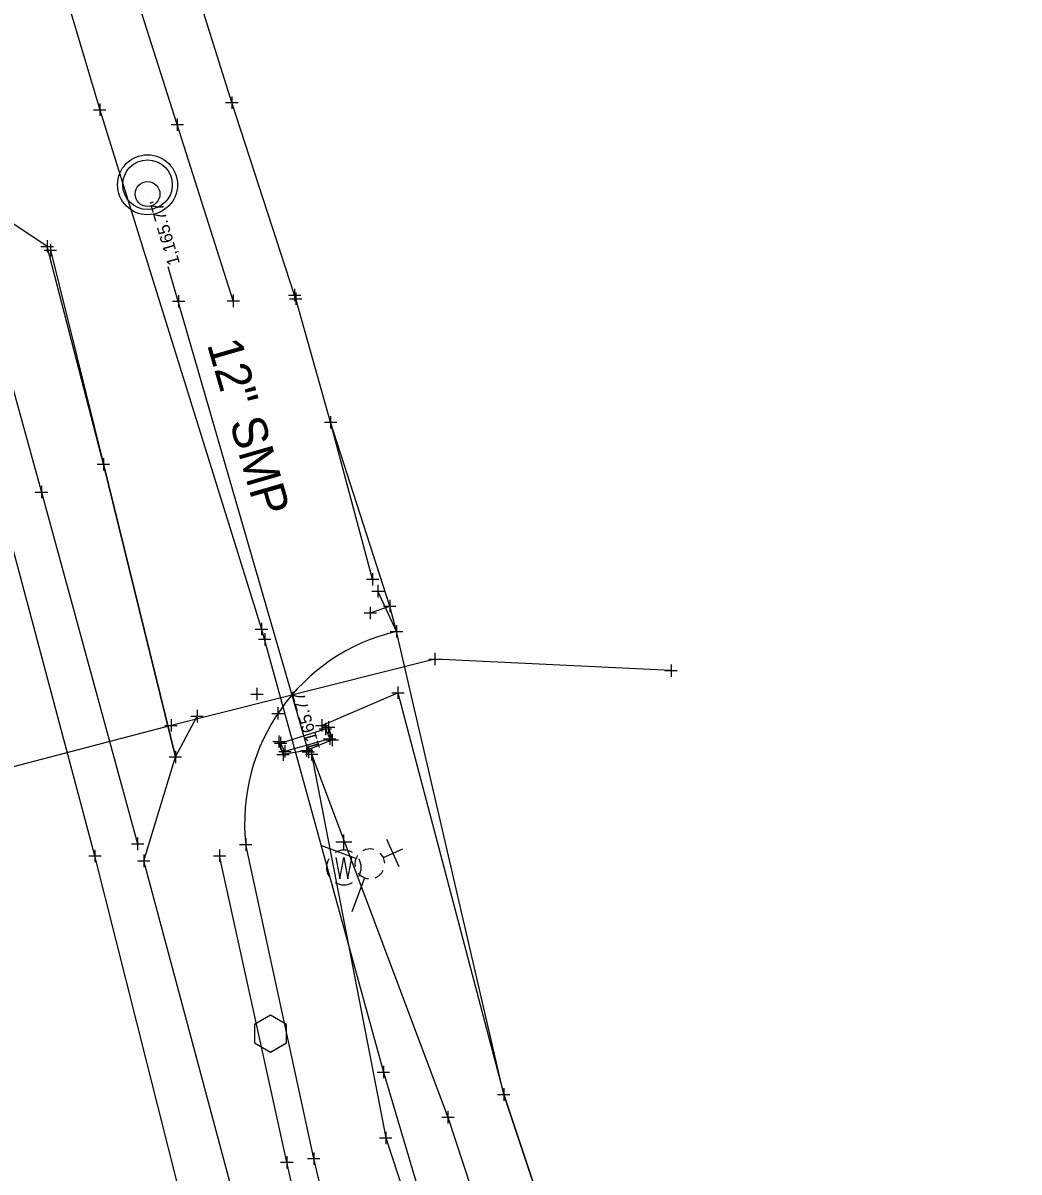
# Model space of a CAD drawing. Extents: x 2324380 to 2325559, y 691096 to 693386.
# Drawn here: x 2325128.4 to 2325208.8, y 691972.1 to 692064.7 of the extents above; entities that cross this region are included whole.
import ezdxf

# ---------------------------------------------------------------- set-up
doc = ezdxf.new("R2010")
doc.units = 0
for name, color, linetype in [('DR_X_Cells', 7, 'Continuous'), ('DR_X_Elev_Flow', 7, 'Continuous'), ('DR_X_Headwall', 7, 'Continuous'), ('DR_X_Storm_Sewer', 7, 'Continuous'), ('DR_X_Text', 7, 'Continuous'), ('GK_Drainage_Nodes', 7, 'Continuous'), ('PM_X_Transverse_Line', 7, 'Continuous'), ('PV_X_Driveway', 7, 'Continuous'), ('PV_X_EOP', 7, 'Continuous'), ('PV_X_Shoulder_Aggregate', 7, 'Continuous'), ('PV_X_Walk', 7, 'Continuous'), ('RD_X_Cells', 7, 'Continuous'), ('RD_X_GR_Rt', 7, 'Continuous'), ('SC_Scratch1', 7, 'Continuous'), ('SV_X_Break_Lines', 7, 'Continuous'), ('SV_X_Shot_Marker', 7, 'Continuous'), ('SV_X_Terrain_Boundary', 7, 'Continuous'), ('SV_X_Toe_of_Slope', 7, 'Continuous'), ('SV_X_Top_of_Bank', 7, 'Continuous'), ('UT_X_Gas', 7, 'Continuous'), ('UT_X_Water', 7, 'Continuous'), ('UT_X_Water_Cells', 7, 'Continuous')]:
    doc.layers.add(name, color=color, linetype=linetype)

msp = doc.modelspace()

# ---------------------------------------------------------------- linework, layer by layer
at = {"layer": 'DR_X_Cells'}
for centre, radius in [((2325138.489, 692051.697), 2.417), ((2325138.489, 692051.697), 2), ((2325138.489, 692050.947), 1)]:
    msp.add_circle(centre, radius, dxfattribs=at)
at = {"layer": 'DR_X_Elev_Flow'}
for p, q in [((2325151.459, 692006.478), (2325151.459, 692005.478)), ((2325150.959, 692005.978), (2325151.959, 692005.978)), ((2325151.459, 692005.978), (2325151.459, 692005.978))]:
    msp.add_line(p, q, dxfattribs=at)
at = {"layer": 'DR_X_Headwall'}
msp.add_lwpolyline([(2325152.828, 692007.837), (2325153.185, 692007.047), (2325149.569, 692006.028), (2325149.216, 692006.692)], close=True, dxfattribs=at)
at = {"layer": 'DR_X_Storm_Sewer'}
msp.add_line((2325151.459, 692005.978), (2325140.151, 692045.092), dxfattribs=at)
at = {"layer": 'GK_Drainage_Nodes'}
for p, q in [((2325138.489, 692053.697), (2325138.489, 692053.697)), ((2325138.489, 692051.697), (2325138.489, 692051.697)), ((2325138.489, 692051.697), (2325138.489, 692051.697)), ((2325138.489, 692050.947), (2325138.489, 692050.947)), ((2325138.489, 692049.697), (2325138.489, 692049.697))]:
    msp.add_line(p, q, dxfattribs=at)
msp.add_circle((2325138.489, 692051.697), 2, dxfattribs=at)
at = {"layer": 'PM_X_Transverse_Line'}
msp.add_lwpolyline([(2325208.031, 691604.619), (2325194.767, 691694.589), (2325190.218, 691721.345), (2325186.042, 691748.471), (2325180.662, 691777.723), (2325175.443, 691810.812), (2325170.122, 691836.608), (2325164.914, 691862.726), (2325159.595, 691887.988), (2325154.325, 691913.687), (2325148, 691940.383), (2325141.011, 691970.752), (2325134.246, 691997.599), (2325126.612, 692026.24), (2325119.986, 692049.571), (2325112.237, 692077.635)], dxfattribs=at)
at = {"layer": 'PV_X_Driveway'}
for p, q in [((2325130.663, 692046.423), (2325134.934, 692029.169)), ((2325153.247, 692032.554), (2325150.44, 692042.514)), ((2325156.635, 692019.901), (2325153.247, 692032.554)), ((2325134.934, 692029.169), (2325140.741, 692005.582)), ((2325140.741, 692005.582), (2325142.488, 692008.863))]:
    msp.add_line(p, q, dxfattribs=at)
at = {"layer": 'PV_X_EOP'}
msp.add_lwpolyline([(2325211.918, 691605.386), (2325210.367, 691618.546), (2325213.959, 691624.804), (2325210.034, 691657.833), (2325203.565, 691662.571), (2325202.33, 691668.932), (2325198.243, 691695.477), (2325193.907, 691721.989), (2325189.381, 691749.914), (2325184.426, 691778.627), (2325178.884, 691811.262), (2325173.941, 691837.313), (2325168.715, 691863.962), (2325163.821, 691888.364), (2325158.392, 691913.65), (2325152.294, 691941.349), (2325145.116, 691971.334), (2325138.187, 691997.205), (2325140.741, 692005.582), (2325134.934, 692029.169), (2325130.398, 692046.728), (2325123.251, 692051.464), (2325115.822, 692078.513)], dxfattribs=at)
at = {"layer": 'PV_X_Shoulder_Aggregate'}
for p, q in [((2325158.563, 692015.701), (2325157.064, 692018.938)), ((2325151.891, 691973.202), (2325146.411, 691998.522)), ((2325159.251, 691943.083), (2325151.891, 691973.202))]:
    msp.add_line(p, q, dxfattribs=at)
msp.add_arc((2325162.181, 692000.254), 15.865, 103.18124, 186.26782, dxfattribs=at)
at = {"layer": 'PV_X_Walk'}
for points in [[(2325150.345, 692042.806), (2325145.287, 692058.32), (2325137.022, 692084.694), (2325126.836, 692114.846), (2325122.507, 692126.861)], [(2325145.407, 692042.338), (2325140.889, 692056.549), (2325132.558, 692082.735), (2325122.132, 692113.395), (2325118.749, 692123.303)]]:
    msp.add_lwpolyline(points, dxfattribs=at)
at = {"layer": 'RD_X_Cells'}
msp.add_lwpolyline([(2325147.104, 691982.524), (2325148.402, 691981.774), (2325149.7, 691982.524), (2325149.7, 691984.024), (2325148.402, 691984.774), (2325147.104, 691984.024), (2325147.104, 691982.524)], dxfattribs=at)
at = {"layer": 'RD_X_GR_Rt'}
for p, q in [((2325156.447, 692017.186), (2325158.021, 692017.741)), ((2325149.72, 691972.915), (2325144.303, 691997.622)), ((2325156.653, 691942.344), (2325149.72, 691972.915))]:
    msp.add_line(p, q, dxfattribs=at)
at = {"layer": 'SV_X_Break_Lines'}
for points in [[(2325123.247, 692051.066), (2325129.941, 692026.924), (2325137.687, 691998.578)], [(2325153.081, 692007.969), (2325153.381, 692006.955), (2325151.312, 692006.096), (2325149.417, 692005.778), (2325149.087, 692006.813)]]:
    msp.add_lwpolyline(points, dxfattribs=at)
at = {"layer": 'SV_X_Shot_Marker'}
for p, q in [((2325145.287, 692058.82), (2325145.287, 692057.82)), ((2325134.639, 692058.245), (2325134.639, 692057.245)), ((2325144.787, 692058.32), (2325145.787, 692058.32)), ((2325145.287, 692058.32), (2325145.287, 692058.32)), ((2325134.139, 692057.745), (2325135.139, 692057.745)), ((2325134.639, 692057.745), (2325134.639, 692057.745)), ((2325140.889, 692057.049), (2325140.889, 692056.049)), ((2325140.389, 692056.549), (2325141.389, 692056.549)), ((2325140.889, 692056.549), (2325140.889, 692056.549)), ((2325130.398, 692047.228), (2325130.398, 692046.228)), ((2325130.663, 692046.923), (2325130.663, 692045.923)), ((2325129.898, 692046.728), (2325130.898, 692046.728)), ((2325130.163, 692046.423), (2325131.163, 692046.423)), ((2325130.398, 692046.728), (2325130.398, 692046.728)), ((2325130.663, 692046.423), (2325130.663, 692046.423)), ((2325150.345, 692043.306), (2325150.345, 692042.306)), ((2325140.497, 692042.302), (2325141.497, 692042.302)), ((2325140.997, 692042.802), (2325140.997, 692041.802)), ((2325140.997, 692042.302), (2325140.997, 692042.302)), ((2325144.907, 692042.338), (2325145.907, 692042.338)), ((2325145.407, 692042.838), (2325145.407, 692041.838)), ((2325145.407, 692042.338), (2325145.407, 692042.338)), ((2325149.845, 692042.806), (2325150.845, 692042.806)), ((2325149.94, 692042.514), (2325150.94, 692042.514)), ((2325150.345, 692042.806), (2325150.345, 692042.806)), ((2325150.44, 692043.014), (2325150.44, 692042.014)), ((2325150.44, 692042.514), (2325150.44, 692042.514)), ((2325153.247, 692033.054), (2325153.247, 692032.054)), ((2325152.747, 692032.554), (2325153.747, 692032.554)), ((2325153.247, 692032.554), (2325153.247, 692032.554)), ((2325134.934, 692029.669), (2325134.934, 692028.669)), ((2325134.934, 692029.669), (2325134.934, 692028.669)), ((2325134.434, 692029.169), (2325135.434, 692029.169)), ((2325134.434, 692029.169), (2325135.434, 692029.169)), ((2325134.934, 692029.169), (2325134.934, 692029.169)), ((2325134.934, 692029.169), (2325134.934, 692029.169)), ((2325129.941, 692027.424), (2325129.941, 692026.424)), ((2325129.441, 692026.924), (2325130.441, 692026.924)), ((2325129.941, 692026.924), (2325129.941, 692026.924)), ((2325156.635, 692020.401), (2325156.635, 692019.401)), ((2325156.135, 692019.901), (2325157.135, 692019.901)), ((2325156.635, 692019.901), (2325156.635, 692019.901)), ((2325157.064, 692019.438), (2325157.064, 692018.438)), ((2325156.564, 692018.938), (2325157.564, 692018.938)), ((2325157.064, 692018.938), (2325157.064, 692018.938)), ((2325158.021, 692018.241), (2325158.021, 692017.241)), ((2325155.947, 692017.186), (2325156.947, 692017.186)), ((2325156.447, 692017.686), (2325156.447, 692016.686)), ((2325156.447, 692017.186), (2325156.447, 692017.186)), ((2325157.521, 692017.741), (2325158.521, 692017.741)), ((2325158.021, 692017.741), (2325158.021, 692017.741)), ((2325147.677, 692016.387), (2325147.677, 692015.387)), ((2325147.177, 692015.887), (2325148.177, 692015.887)), ((2325147.677, 692015.887), (2325147.677, 692015.887)), ((2325147.935, 692015.561), (2325147.935, 692014.561)), ((2325158.063, 692015.701), (2325159.063, 692015.701)), ((2325158.563, 692016.201), (2325158.563, 692015.201)), ((2325158.563, 692015.701), (2325158.563, 692015.701)), ((2325147.435, 692015.061), (2325148.435, 692015.061)), ((2325147.935, 692015.061), (2325147.935, 692015.061)), ((2325161.167, 692013.468), (2325162.167, 692013.468)), ((2325161.667, 692013.968), (2325161.667, 692012.968)), ((2325161.667, 692013.468), (2325161.667, 692013.468)), ((2325180.199, 692012.533), (2325181.199, 692012.533)), ((2325180.699, 692013.033), (2325180.699, 692012.033)), ((2325180.699, 692012.533), (2325180.699, 692012.533)), ((2325147.308, 692011.149), (2325147.308, 692010.149)), ((2325158.174, 692010.756), (2325159.174, 692010.756)), ((2325158.674, 692011.256), (2325158.674, 692010.256)), ((2325158.674, 692010.756), (2325158.674, 692010.756)), ((2325146.808, 692010.649), (2325147.808, 692010.649)), ((2325147.308, 692010.649), (2325147.308, 692010.649)), ((2325141.988, 692008.863), (2325142.988, 692008.863)), ((2325142.488, 692009.363), (2325142.488, 692008.363)), ((2325142.488, 692008.863), (2325142.488, 692008.863)), ((2325148.504, 692009.09), (2325149.504, 692009.09)), ((2325149.004, 692009.59), (2325149.004, 692008.59)), ((2325149.004, 692009.09), (2325149.004, 692009.09)), ((2325139.885, 692008.126), (2325140.885, 692008.126)), ((2325140.385, 692008.626), (2325140.385, 692007.626)), ((2325140.385, 692008.126), (2325140.385, 692008.126)), ((2325152.044, 692008.126), (2325153.044, 692008.126)), ((2325152.544, 692008.626), (2325152.544, 692007.626)), ((2325152.544, 692008.126), (2325152.544, 692008.126)), ((2325152.581, 692007.969), (2325153.581, 692007.969)), ((2325152.828, 692008.337), (2325152.828, 692007.337)), ((2325153.081, 692008.469), (2325153.081, 692007.469)), ((2325153.081, 692007.969), (2325153.081, 692007.969)), ((2325149.087, 692007.313), (2325149.087, 692006.313)), ((2325149.216, 692007.192), (2325149.216, 692006.192)), ((2325152.328, 692007.837), (2325153.328, 692007.837)), ((2325152.685, 692007.047), (2325153.685, 692007.047)), ((2325152.828, 692007.837), (2325152.828, 692007.837)), ((2325153.185, 692007.547), (2325153.185, 692006.547)), ((2325153.185, 692007.047), (2325153.185, 692007.047)), ((2325153.381, 692007.455), (2325153.381, 692006.455)), ((2325140.741, 692006.082), (2325140.741, 692005.082)), ((2325140.741, 692006.082), (2325140.741, 692005.082)), ((2325148.587, 692006.813), (2325149.587, 692006.813)), ((2325148.716, 692006.692), (2325149.716, 692006.692)), ((2325149.087, 692006.813), (2325149.087, 692006.813)), ((2325149.216, 692006.692), (2325149.216, 692006.692)), ((2325149.417, 692006.278), (2325149.417, 692005.278)), ((2325149.569, 692006.528), (2325149.569, 692005.528)), ((2325150.812, 692006.096), (2325151.812, 692006.096)), ((2325151.312, 692006.596), (2325151.312, 692005.596)), ((2325151.312, 692006.096), (2325151.312, 692006.096)), ((2325151.717, 692006.298), (2325151.717, 692005.298)), ((2325151.717, 692006.298), (2325151.717, 692005.298)), ((2325152.881, 692006.955), (2325153.881, 692006.955)), ((2325153.381, 692006.955), (2325153.381, 692006.955)), ((2325140.241, 692005.582), (2325141.241, 692005.582)), ((2325140.241, 692005.582), (2325141.241, 692005.582)), ((2325140.741, 692005.582), (2325140.741, 692005.582)), ((2325140.741, 692005.582), (2325140.741, 692005.582)), ((2325148.917, 692005.778), (2325149.917, 692005.778)), ((2325149.069, 692006.028), (2325150.069, 692006.028)), ((2325149.417, 692005.778), (2325149.417, 692005.778)), ((2325149.569, 692006.028), (2325149.569, 692006.028)), ((2325151.217, 692005.798), (2325152.217, 692005.798)), ((2325151.217, 692005.798), (2325152.217, 692005.798)), ((2325151.717, 692005.798), (2325151.717, 692005.798)), ((2325151.717, 692005.798), (2325151.717, 692005.798)), ((2325137.687, 691999.078), (2325137.687, 691998.078)), ((2325146.411, 691999.022), (2325146.411, 691998.022)), ((2325134.246, 691998.099), (2325134.246, 691997.099)), ((2325137.187, 691998.578), (2325138.187, 691998.578)), ((2325137.687, 691998.578), (2325137.687, 691998.578)), ((2325138.187, 691997.705), (2325138.187, 691996.705)), ((2325144.303, 691998.122), (2325144.303, 691997.122)), ((2325145.911, 691998.522), (2325146.911, 691998.522)), ((2325146.411, 691998.522), (2325146.411, 691998.522)), ((2325133.746, 691997.599), (2325134.746, 691997.599)), ((2325134.246, 691997.599), (2325134.246, 691997.599)), ((2325137.687, 691997.205), (2325138.687, 691997.205)), ((2325138.187, 691997.205), (2325138.187, 691997.205)), ((2325143.803, 691997.622), (2325144.803, 691997.622)), ((2325144.303, 691997.622), (2325144.303, 691997.622)), ((2325157.011, 691980.18), (2325158.011, 691980.18)), ((2325157.511, 691980.68), (2325157.511, 691979.68)), ((2325157.511, 691980.18), (2325157.511, 691980.18)), ((2325166.706, 691978.375), (2325167.706, 691978.375)), ((2325167.206, 691978.875), (2325167.206, 691977.875)), ((2325167.206, 691978.375), (2325167.206, 691978.375)), ((2325162.21, 691976.546), (2325163.21, 691976.546)), ((2325162.71, 691977.046), (2325162.71, 691976.046)), ((2325162.71, 691976.546), (2325162.71, 691976.546)), ((2325157.191, 691974.871), (2325158.191, 691974.871)), ((2325157.691, 691975.371), (2325157.691, 691974.371)), ((2325157.691, 691974.871), (2325157.691, 691974.871)), ((2325151.891, 691973.702), (2325151.891, 691972.702)), ((2325149.22, 691972.915), (2325150.22, 691972.915)), ((2325149.72, 691973.415), (2325149.72, 691972.415)), ((2325149.72, 691972.915), (2325149.72, 691972.915)), ((2325151.391, 691973.202), (2325152.391, 691973.202)), ((2325151.891, 691973.202), (2325151.891, 691973.202))]:
    msp.add_line(p, q, dxfattribs=at)
at = {"layer": 'SV_X_Terrain_Boundary'}
msp.add_lwpolyline([(2325352.933, 691883.659), (2325255.311, 691863.891), (2325186.043, 691921.872), (2325167.206, 691978.375), (2325158.563, 692015.701), (2325158.021, 692017.741), (2325153.247, 692032.554), (2325150.44, 692042.514), (2325150.345, 692042.806), (2325145.287, 692058.32), (2325137.022, 692084.694)], dxfattribs=at)
at = {"layer": 'SV_X_Toe_of_Slope'}
for points in [[(2325151.717, 692005.798), (2325157.691, 691974.871), (2325176.194, 691918.403), (2325187.809, 691869.152), (2325196.671, 691845.991), (2325199.142, 691833.728)], [(2325151.717, 692005.798), (2325162.71, 691976.546), (2325181.201, 691920.276), (2325195.806, 691870.258), (2325202.361, 691849.073), (2325202.361, 691835.591)]]:
    msp.add_lwpolyline(points, dxfattribs=at)
at = {"layer": 'SV_X_Top_of_Bank'}
msp.add_lwpolyline([(2325152.544, 692008.126), (2325158.674, 692010.756), (2325167.206, 691978.375), (2325186.043, 691921.872), (2325201.379, 691871.384), (2325207.218, 691852.964), (2325225.302, 691856.36), (2325255.311, 691863.891)], dxfattribs=at)
at = {"layer": 'UT_X_Gas'}
msp.add_lwpolyline([(2325180.699, 692012.533), (2325161.667, 692013.468), (2325140.385, 692008.126), (2325120.132, 692002.823), (2325102.157, 691998.254), (2325087.784, 691995.252)], dxfattribs=at)
at = {"layer": 'UT_X_Water'}
msp.add_lwpolyline([(2325124.52, 692091.666), (2325134.639, 692057.745), (2325147.677, 692015.887), (2325157.511, 691980.18), (2325171.318, 691933.622), (2325182.702, 691894.576), (2325195.308, 691848.427), (2325206.623, 691806.006), (2325210.43, 691786.813), (2325214.153, 691760.189), (2325217.411, 691715.895), (2325220.598, 691667.669), (2325222.982, 691628.174), (2325224.503, 691603.216), (2325224.967, 691587.75)], dxfattribs=at)
at = {"layer": 'UT_X_Water_Cells'}
for p, q in [((2325154.956, 691998.702), (2325153.684, 691998.702)), ((2325154.321, 691998.065), (2325154.321, 691999.337)), ((2325158.786, 691996.727), (2325157.793, 691998.912)), ((2325155.289, 691997.384), (2325152.537, 691998.417)), ((2325157.507, 691997.463), (2325159.073, 691998.175)), ((2325156.412, 691996.964), (2325156.412, 691996.964)), ((2325156.412, 691996.964), (2325156.412, 691996.964)), ((2325154.321, 691996.665), (2325154.321, 691996.665)), ((2325155.989, 691995.844), (2325154.958, 691993.09))]:
    msp.add_line(p, q, dxfattribs=at)
msp.add_lwpolyline([(2325153.684, 691997.485), (2325154.003, 691995.762), (2325154.321, 691997.485), (2325154.641, 691995.762), (2325154.958, 691997.485)], dxfattribs=at)
for centre, radius, start, end in [((2325154.321, 691996.667), 1.4, 60.01836, 120.01574), ((2325156.412, 691996.964), 1.2, 74.46326, 118.5052), ((2325156.412, 691996.964), 1.2, 2.58173, 46.48025), ((2325154.321, 691996.667), 1.4, 150.01836, 209.98164), ((2325156.412, 691996.964), 1.2, 146.32104, 190.2902), ((2325154.321, 691996.667), 1.4, 330.01836, 29.98164), ((2325156.412, 691996.964), 1.2, 218.26616, 264.35194), ((2325156.412, 691996.964), 1.2, 290.45874, 334.43112), ((2325154.321, 691996.667), 1.4, 239.98426, 299.98164)]:
    msp.add_arc(centre, radius, start, end, dxfattribs=at)

# ---------------------------------------------------------------- texts
at = {"layer": 'DR_X_Text'}
msp.add_text('12" SMP', height=2.8, rotation=286.12495, dxfattribs=at).set_placement((2325143.269, 692038.844))
at = {"layer": 'SC_Scratch1'}
for s, p in [("1,165.77'", (2325141.111, 692045.37)), ("1165.77'", (2325152.42, 692006.255))]:
    msp.add_text(s, height=1, rotation=106.12495, dxfattribs=at).set_placement(p)

doc.saveas('drawing.dxf')
